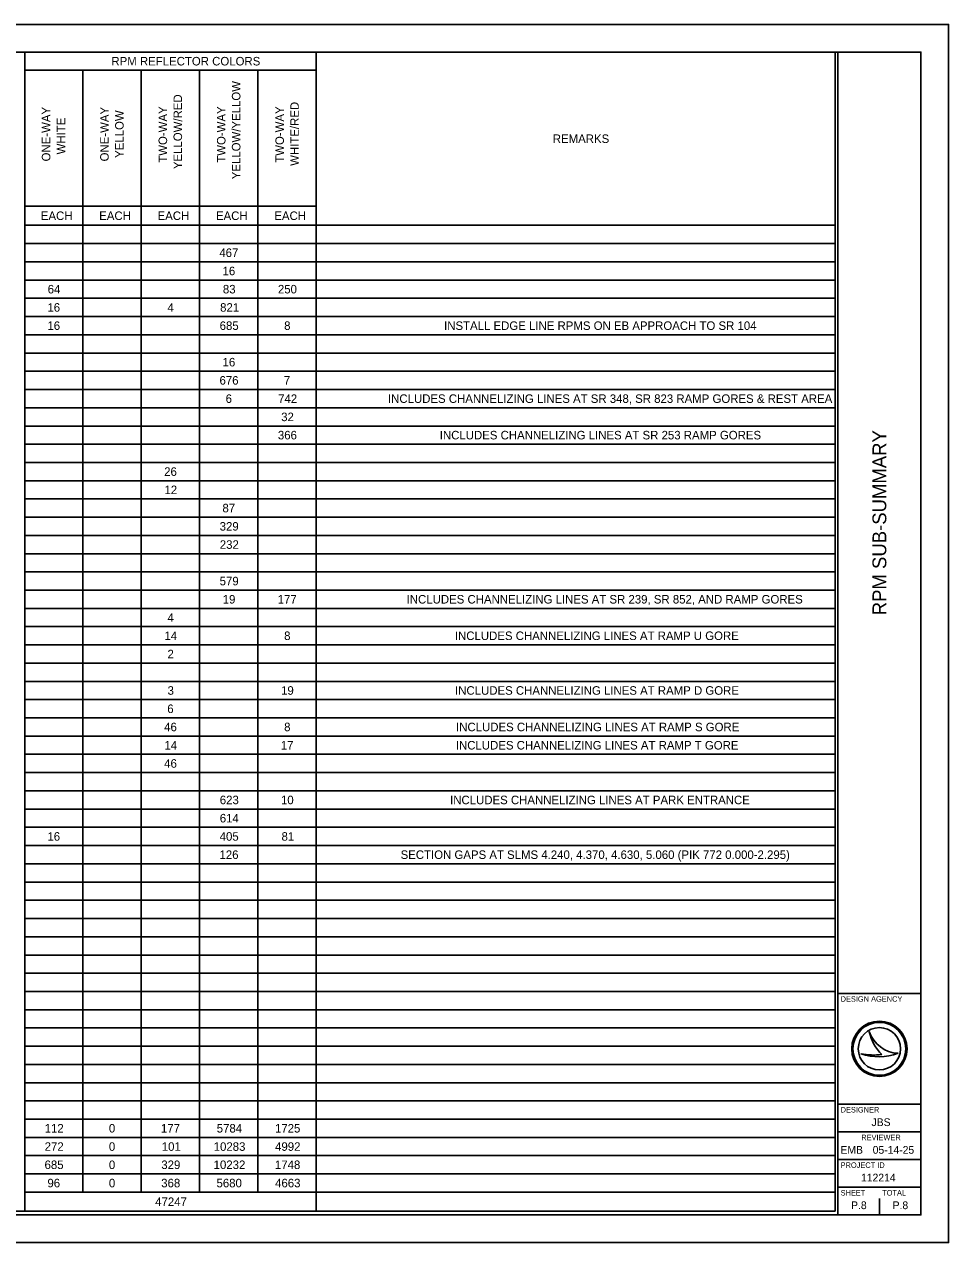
# Model space of a CAD drawing. Extents: x 0 to 34, y 0 to 22.
# Drawn here: x 17.31 to 34, y 0 to 22 of the extents above; entities that cross this region are included whole.
import ezdxf

# ---------------------------------------------------------------- set-up
doc = ezdxf.new("R2010")
doc.units = 0
for name, color, linetype in [('Default', 7, 'Continuous'), ('SH_Border', 7, 'Continuous'), ('SH_Cut_Line', 7, 'Continuous'), ('SH_Data', 7, 'Continuous')]:
    doc.layers.add(name, color=color, linetype=linetype)

msp = doc.modelspace()

# ---------------------------------------------------------------- linework, layer by layer
at = {"layer": 'Default'}
for p, q in [((15.193, 21.5), (17.323, 21.5)), ((17.301, 21.5), (31.954, 21.5)), ((17.323, 21.5), (17.323, 0.566)), ((22.582, 21.5), (22.582, 0.566)), ((31.954, 21.5), (31.954, 0.566)), ((17.323, 21.171), (22.582, 21.171)), ((18.366, 21.171), (18.366, 0.912)), ((19.42, 21.171), (19.42, 0.912)), ((20.474, 21.171), (20.474, 0.912)), ((21.528, 21.171), (21.528, 0.912)), ((17.323, 18.716), (22.582, 18.716)), ((17.323, 18.371), (31.954, 18.371)), ((17.323, 18.041), (31.954, 18.041)), ((17.323, 17.712), (31.954, 17.712)), ((17.323, 17.382), (31.954, 17.382)), ((17.323, 17.053), (31.954, 17.053)), ((17.323, 16.724), (31.954, 16.724)), ((17.323, 16.394), (31.954, 16.394)), ((17.323, 16.065), (31.954, 16.065)), ((17.323, 15.735), (31.954, 15.735)), ((17.323, 15.406), (31.954, 15.406)), ((17.323, 15.076), (31.954, 15.076)), ((17.323, 14.747), (31.954, 14.747)), ((17.323, 14.418), (31.954, 14.418)), ((17.323, 14.088), (31.954, 14.088)), ((17.323, 13.759), (31.954, 13.759)), ((17.323, 13.429), (31.954, 13.429)), ((17.323, 13.1), (31.954, 13.1)), ((17.323, 12.771), (31.954, 12.771)), ((17.323, 12.441), (31.954, 12.441)), ((17.323, 12.112), (31.954, 12.112)), ((17.323, 11.782), (31.954, 11.782)), ((17.323, 11.453), (31.954, 11.453)), ((17.323, 11.124), (31.954, 11.124)), ((17.323, 10.794), (31.954, 10.794)), ((17.323, 10.465), (31.954, 10.465)), ((17.323, 10.135), (31.954, 10.135)), ((17.323, 9.806), (31.954, 9.806)), ((17.323, 9.476), (31.954, 9.476)), ((17.323, 9.147), (31.954, 9.147)), ((17.323, 8.818), (31.954, 8.818)), ((17.323, 8.488), (31.954, 8.488)), ((17.323, 8.159), (31.954, 8.159)), ((17.323, 7.829), (31.954, 7.829)), ((17.323, 7.5), (31.954, 7.5)), ((17.323, 7.171), (31.954, 7.171)), ((17.323, 6.841), (31.954, 6.841)), ((17.323, 6.512), (31.954, 6.512)), ((17.323, 6.182), (31.954, 6.182)), ((17.323, 5.853), (31.954, 5.853)), ((17.323, 5.524), (31.954, 5.524)), ((17.323, 5.194), (31.954, 5.194)), ((17.323, 4.865), (31.954, 4.865)), ((17.323, 4.535), (31.954, 4.535)), ((17.323, 4.206), (31.954, 4.206)), ((17.323, 3.876), (31.954, 3.876)), ((17.323, 3.547), (31.954, 3.547)), ((17.323, 3.218), (31.954, 3.218)), ((17.323, 2.888), (31.954, 2.888)), ((17.323, 2.559), (31.954, 2.559)), ((17.323, 2.229), (31.954, 2.229)), ((17.323, 1.9), (31.954, 1.9)), ((17.323, 1.571), (31.954, 1.571)), ((17.323, 1.241), (31.954, 1.241)), ((17.323, 0.912), (31.954, 0.912)), ((15.193, 0.566), (17.323, 0.566)), ((17.301, 0.566), (31.954, 0.566))]:
    msp.add_line(p, q, dxfattribs=at)
at = {"layer": 'SH_Border'}
for p, q in [((32, 0.5), (32, 21.5)), ((32, 4.5), (33.5, 4.5)), ((32, 2.5), (33.5, 2.5)), ((32, 2), (33.5, 2)), ((32, 1.5), (33.5, 1.5)), ((32, 1), (33.5, 1))]:
    msp.add_line(p, q, dxfattribs=at)
msp.add_lwpolyline([(1.5, 21.5), (33.5, 21.5), (33.5, 0.5), (1.5, 0.5)], close=True, dxfattribs=at)
at = {"layer": 'SH_Cut_Line'}
msp.add_lwpolyline([(0, 0), (34, 0), (34, 22), (0, 22)], close=True, dxfattribs=at)
at = {"layer": 'SH_Data'}
for p, q in [((32.567, 3.81), (32.567, 3.81)), ((32.417, 3.41), (32.417, 3.41)), ((32.75, 3.5), (32.75, 3.5)), ((33.087, 3.419), (33.087, 3.419)), ((32.375, 0.675), (32.375, 0.675)), ((32.75, 0.5), (32.75, 0.8))]:
    msp.add_line(p, q, dxfattribs=at)
for radius in [0.5, 0.477, 0.477, 0.382]:
    msp.add_circle((32.75, 3.5), radius, dxfattribs=at)
for centre, radius, start, end in [((33.116, 3.998), 0.58, 198.9257, 198.9319), ((33.347, 3.97), 0.796, 191.6379, 191.6421), ((33.116, 3.998), 0.58, 198.9319, 267.1657), ((33.347, 3.97), 0.796, 191.6421, 226.0947), ((32.739, 4.37), 1.013, 251.4576, 290.0832), ((32.648, 4.654), 1.266, 259.4964, 259.4995), ((32.739, 4.37), 1.013, 251.4527, 251.4576), ((32.648, 4.654), 1.266, 259.4995, 276.6672)]:
    msp.add_arc(centre, radius, start, end, dxfattribs=at)

# ---------------------------------------------------------------- texts
at = {"layer": 'Default'}
for s, p in [('RPM REFLECTOR COLORS', (18.883, 21.258)), ('REMARKS', (26.853, 19.858)), ('EACH', (17.609, 18.467)), ('EACH', (18.663, 18.467)), ('EACH', (19.717, 18.467)), ('EACH', (20.771, 18.467)), ('EACH', (21.825, 18.467)), ('467', (20.832, 17.799)), ('16', (20.89, 17.47)), ('64', (17.733, 17.141)), ('83', (20.896, 17.141)), ('250', (21.89, 17.141)), ('16', (17.728, 16.811)), ('4', (19.896, 16.811)), ('821', (20.846, 16.811)), ('16', (17.728, 16.482)), ('685', (20.838, 16.482)), ('8', (22.002, 16.482)), ('INSTALL EDGE LINE RPMS ON EB APPROACH TO SR 104', (24.89, 16.482)), ('16', (20.89, 15.823)), ('676', (20.835, 15.494)), ('7', (21.997, 15.494)), ('6', (20.946, 15.164)), ('742', (21.894, 15.164)), ('INCLUDES CHANNELIZING LINES AT SR 348, SR 823 RAMP GORES & REST AREA', (23.877, 15.164)), ('32', (21.949, 14.835)), ('366', (21.889, 14.505)), ('INCLUDES CHANNELIZING LINES AT SR 253 RAMP GORES', (24.812, 14.505)), ('26', (19.836, 13.847)), ('12', (19.841, 13.517)), ('87', (20.888, 13.188)), ('329', (20.838, 12.858)), ('232', (20.84, 12.529)), ('579', (20.838, 11.87)), ('19', (20.893, 11.541)), ('177', (21.886, 11.541)), ('INCLUDES CHANNELIZING LINES AT SR 239, SR 852, AND RAMP GORES', (24.214, 11.541)), ('4', (19.896, 11.211)), ('14', (19.841, 10.882)), ('8', (22.002, 10.882)), ('INCLUDES CHANNELIZING LINES AT RAMP U GORE', (25.085, 10.882)), ('2', (19.896, 10.552)), ('3', (19.897, 9.894)), ('19', (21.947, 9.894)), ('INCLUDES CHANNELIZING LINES AT RAMP D GORE', (25.088, 9.894)), ('6', (19.892, 9.564)), ('46', (19.836, 9.235)), ('8', (22.002, 9.235)), ('INCLUDES CHANNELIZING LINES AT RAMP S GORE', (25.106, 9.235)), ('14', (19.841, 8.905)), ('17', (21.942, 8.905)), ('INCLUDES CHANNELIZING LINES AT RAMP T GORE', (25.102, 8.905)), ('46', (19.836, 8.576)), ('623', (20.84, 7.917)), ('10', (21.945, 7.917)), ('INCLUDES CHANNELIZING LINES AT PARK ENTRANCE', (24.998, 7.917)), ('614', (20.84, 7.588)), ('16', (17.728, 7.258)), ('405', (20.838, 7.258)), ('81', (21.955, 7.258)), ('126', (20.835, 6.929)), ('SECTION GAPS AT SLMS 4.240, 4.370, 4.630, 5.060 (PIK 772 0.000-2.295)', (24.105, 6.929)), ('112', (17.678, 1.988)), ('0', (18.838, 1.988)), ('177', (19.778, 1.988)), ('5784', (20.785, 1.988)), ('1725', (21.837, 1.988)), ('272', (17.678, 1.658)), ('0', (18.838, 1.658)), ('101', (19.792, 1.658)), ('10283', (20.73, 1.658)), ('4992', (21.839, 1.658)), ('685', (17.676, 1.329)), ('0', (18.838, 1.329)), ('329', (19.784, 1.329)), ('10232', (20.729, 1.329)), ('1748', (21.836, 1.329)), ('96', (17.728, 0.999)), ('0', (18.838, 0.999)), ('368', (19.783, 0.999)), ('5680', (20.781, 0.999)), ('4663', (21.839, 0.999)), ('47247', (19.674, 0.662))]:
    msp.add_text(s, height=0.154, dxfattribs=at).set_placement(p)
for s, p in [('YELLOW/YELLOW', (21.213, 19.203)), ('YELLOW/RED', (20.159, 19.386)), ('ONE-WAY ', (17.781, 19.525)), ('ONE-WAY', (18.835, 19.525)), ('TWO-WAY', (19.889, 19.501)), ('TWO-WAY', (20.943, 19.501)), ('TWO-WAY', (21.998, 19.501)), ('WHITE/RED', (22.267, 19.445)), ('WHITE', (18.051, 19.652)), ('YELLOW', (19.105, 19.589))]:
    msp.add_text(s, height=0.154, rotation=90, dxfattribs=at).set_placement(p)
at = {"layer": 'SH_Data'}
msp.add_text('RPM SUB-SUMMARY', height=0.25, rotation=90, dxfattribs=at).set_placement((32.875, 11.329))
for s, height, p in [('DESIGN AGENCY', 0.1, (32.05, 4.35)), ('DESIGNER', 0.1, (32.05, 2.35)), ('JBS', 0.14, (32.608, 2.105)), ('REVIEWER', 0.1, (32.422, 1.85)), ('EMB', 0.14, (32.047, 1.605)), ('05-14-25', 0.14, (32.629, 1.605)), ('PROJECT ID', 0.1, (32.05, 1.35)), ('112214', 0.14, (32.418, 1.105)), ('SHEET', 0.1, (32.05, 0.85)), ('TOTAL', 0.1, (32.8, 0.85)), ('P.8', 0.14, (32.239, 0.605)), ('P.8', 0.14, (32.989, 0.605))]:
    msp.add_text(s, height=height, dxfattribs=at).set_placement(p)

doc.saveas('drawing.dxf')
